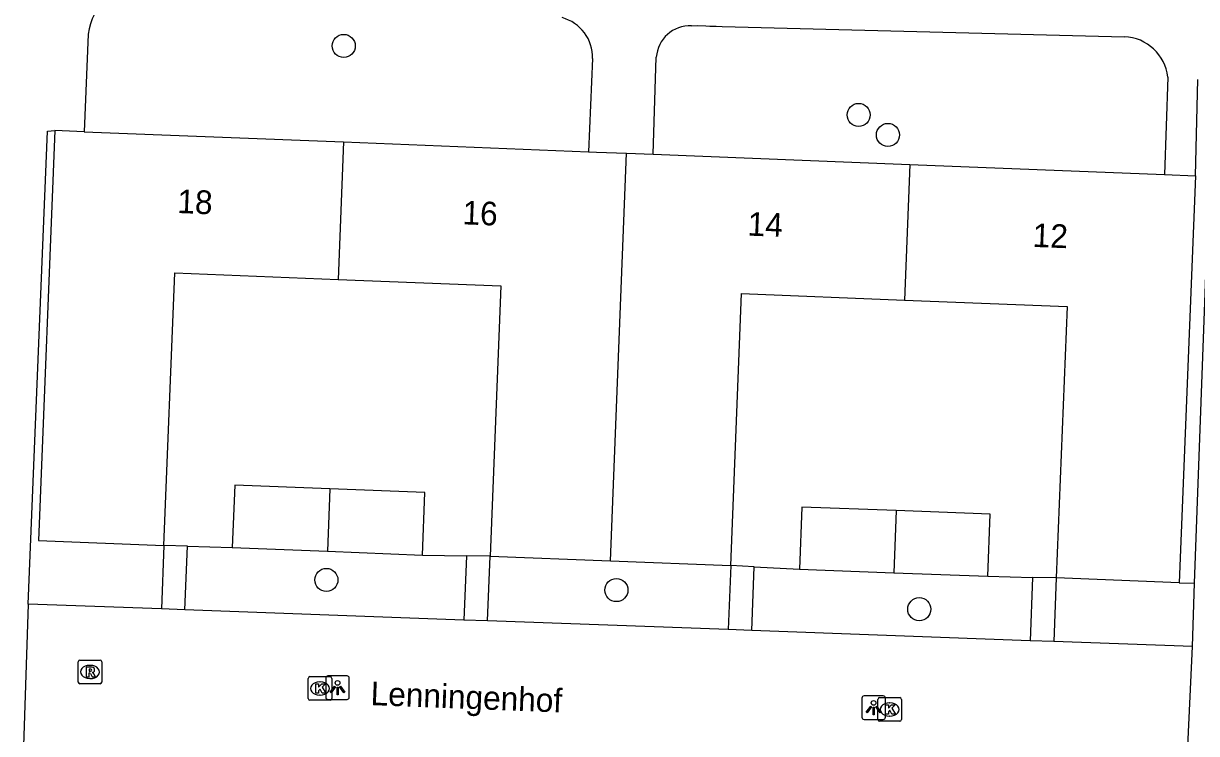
# Model space of a CAD drawing. Extents: x 160787 to 161428, y 386828 to 387483.
# Drawn here: x 161186.98 to 161236.62, y 387037.65 to 387067.7 of the extents above; entities that cross this region are included whole.
import ezdxf

# ---------------------------------------------------------------- set-up
doc = ezdxf.new("R2010")
doc.units = 0
for name, color, linetype in [('IMGEO_Boom', 7, 'Continuous'), ('IMGEO_Groenvoorziening', 7, 'Continuous'), ('IMGEO_Kolk', 7, 'Continuous'), ('IMGEO_Lichtpunt', 7, 'Continuous'), ('IMGEO_Openbare_ruimte_label', 7, 'Continuous'), ('IMGEO_Pand', 7, 'Continuous'), ('IMGEO_Pand_nummerreeks', 7, 'Continuous'), ('IMGEO_Rioolput', 7, 'Continuous'), ('IMGEO_Voetpad_open', 7, 'Continuous')]:
    doc.layers.add(name, color=color, linetype=linetype)

msp = doc.modelspace()

# ---------------------------------------------------------------- linework, layer by layer
at = {"layer": 'IMGEO_Boom'}
for centre in [(161200.531, 387066.744), (161222.319, 387063.825), (161223.558, 387062.978), (161199.795, 387044.146), (161212.067, 387043.717), (161224.883, 387042.909)]:
    msp.add_circle(centre, 0.489, dxfattribs=at)
at = {"layer": 'IMGEO_Groenvoorziening'}
for points in [[(161193.92, 387045.577), (161195.817, 387045.517)], [(161203.862, 387045.199), (161205.724, 387045.174)], [(161217.902, 387044.703), (161219.82, 387044.6)], [(161227.788, 387044.301), (161229.681, 387044.255)], [(161235.886, 387044.024), (161236.536, 387044.01)]]:
    msp.add_lwpolyline(points, dxfattribs=at)
at = {"layer": 'IMGEO_Kolk'}
for p, q in [((161199.026, 387039.129), (161199.026, 387039.981)), ((161199.101, 387040.055), (161199.953, 387040.055)), ((161200.027, 387039.981), (161200.027, 387039.129)), ((161199.514, 387039.835), (161199.539, 387039.835)), ((161199.953, 387039.055), (161199.101, 387039.055)), ((161199.537, 387039.275), (161199.512, 387039.275)), ((161223.131, 387038.241), (161223.131, 387039.093)), ((161223.206, 387039.167), (161224.058, 387039.167)), ((161224.132, 387039.093), (161224.132, 387038.241)), ((161223.619, 387038.947), (161223.644, 387038.947)), ((161224.058, 387038.167), (161223.206, 387038.167)), ((161223.642, 387038.387), (161223.617, 387038.387))]:
    msp.add_line(p, q, dxfattribs=at)
for points in [[(161199.026, 387039.129), (161199.026, 387039.981)], [(161199.101, 387040.055), (161199.953, 387040.055)], [(161200.027, 387039.981), (161200.027, 387039.129)], [(161199.347, 387039.755), (161199.47, 387039.755), (161199.47, 387039.604), (161199.6, 387039.755), (161199.764, 387039.755), (161199.618, 387039.604), (161199.771, 387039.355), (161199.619, 387039.355), (161199.534, 387039.519), (161199.47, 387039.452), (161199.47, 387039.355), (161199.347, 387039.355), (161199.347, 387039.755)], [(161199.953, 387039.055), (161199.101, 387039.055)], [(161223.131, 387038.241), (161223.131, 387039.093)], [(161223.206, 387039.167), (161224.058, 387039.167)], [(161224.132, 387039.093), (161224.132, 387038.241)], [(161223.452, 387038.867), (161223.575, 387038.867), (161223.575, 387038.716), (161223.705, 387038.867), (161223.869, 387038.867), (161223.723, 387038.716), (161223.876, 387038.467), (161223.724, 387038.467), (161223.639, 387038.631), (161223.575, 387038.564), (161223.575, 387038.467), (161223.452, 387038.467), (161223.452, 387038.867)], [(161224.058, 387038.167), (161223.206, 387038.167)]]:
    msp.add_lwpolyline(points, dxfattribs=at)
for centre, start, end in [((161199.103, 387039.979), 91.552, 178.448), ((161199.103, 387039.979), 91.552, 178.448), ((161199.951, 387039.979), 1.552, 88.448), ((161199.951, 387039.979), 1.552, 88.448), ((161199.103, 387039.131), 181.552, 268.448), ((161199.103, 387039.131), 181.552, 268.448), ((161199.951, 387039.131), 271.552, 358.448), ((161199.951, 387039.131), 271.552, 358.448), ((161223.208, 387039.091), 91.552, 178.448), ((161223.208, 387039.091), 91.552, 178.448), ((161224.056, 387039.091), 1.552, 88.448), ((161224.056, 387039.091), 1.552, 88.448), ((161223.208, 387038.243), 181.552, 268.448), ((161223.208, 387038.243), 181.552, 268.448), ((161224.056, 387038.243), 271.552, 358.448), ((161224.056, 387038.243), 271.552, 358.448)]:
    msp.add_arc(centre, 0.0765, start, end, dxfattribs=at)
for centre, major_axis, ratio, start_param, end_param in [((161199.513, 387039.555), (-0.387, 0.002), 0.722429, 4.712389, 7.853982), ((161199.538, 387039.555), (-0.39, 0.002), 0.717154, 1.570796, 4.712389), ((161223.618, 387038.667), (-0.387, 0.002), 0.722429, 4.712389, 7.853982), ((161223.643, 387038.667), (-0.39, 0.002), 0.717154, 1.570796, 4.712389)]:
    msp.add_ellipse(centre, major_axis=major_axis, ratio=ratio, start_param=start_param, end_param=end_param, dxfattribs=at)
at = {"layer": 'IMGEO_Lichtpunt'}
for p, q in [((161199.77, 387039.994), (161199.77, 387039.187)), ((161199.77, 387039.994), (161199.77, 387039.187)), ((161200.672, 387040.089), (161199.864, 387040.089)), ((161200.672, 387040.089), (161199.864, 387040.089)), ((161200.766, 387039.187), (161200.766, 387039.994)), ((161200.766, 387039.187), (161200.766, 387039.994)), ((161199.864, 387039.093), (161200.672, 387039.093)), ((161199.864, 387039.093), (161200.672, 387039.093)), ((161222.454, 387039.148), (161222.454, 387038.341)), ((161222.454, 387039.148), (161222.454, 387038.341)), ((161223.356, 387039.243), (161222.548, 387039.243)), ((161223.356, 387039.243), (161222.548, 387039.243)), ((161223.45, 387038.341), (161223.45, 387039.148)), ((161223.45, 387038.341), (161223.45, 387039.148)), ((161222.548, 387038.247), (161223.356, 387038.247)), ((161222.548, 387038.247), (161223.356, 387038.247))]:
    msp.add_line(p, q, dxfattribs=at)
for points in [[(161200.144, 387039.658), (161200.183, 387039.63), (161199.995, 387039.368), (161199.957, 387039.395), (161200.144, 387039.658)], [(161200.246, 387039.61), (161200.293, 387039.61), (161200.293, 387039.288), (161200.246, 387039.288), (161200.246, 387039.61)], [(161200.356, 387039.63), (161200.394, 387039.657), (161200.581, 387039.395), (161200.542, 387039.367), (161200.356, 387039.63)], [(161222.828, 387038.812), (161222.867, 387038.784), (161222.679, 387038.522), (161222.641, 387038.549), (161222.828, 387038.812)], [(161222.93, 387038.764), (161222.977, 387038.764), (161222.977, 387038.442), (161222.93, 387038.442), (161222.93, 387038.764)], [(161223.04, 387038.784), (161223.078, 387038.811), (161223.265, 387038.549), (161223.226, 387038.521), (161223.04, 387038.784)]]:
    msp.add_lwpolyline(points, dxfattribs=at)
for centre in [(161200.269, 387039.792), (161222.953, 387038.946)]:
    msp.add_circle(centre, 0.0994, dxfattribs=at)
for centre, start, end in [((161199.864, 387039.994), 90, 180), ((161199.864, 387039.994), 90, 180), ((161200.672, 387039.994), 0, 90), ((161200.672, 387039.994), 0, 90), ((161199.864, 387039.187), 180, 270), ((161199.864, 387039.187), 180, 270), ((161200.672, 387039.187), 270, 0), ((161200.672, 387039.187), 270, 360), ((161222.548, 387039.148), 90, 180), ((161222.548, 387039.148), 90, 180), ((161223.356, 387039.148), 0, 90), ((161223.356, 387039.148), 0, 90), ((161222.548, 387038.341), 180, 270), ((161222.548, 387038.341), 180, 270), ((161223.356, 387038.341), 270, 0), ((161223.356, 387038.341), 270, 360)]:
    msp.add_arc(centre, 0.0946, start, end, dxfattribs=at)
at = {"layer": 'IMGEO_Pand'}
for points in [[(161188.306, 387063.164), (161187.619, 387045.819), (161192.921, 387045.609)], [(161189.542, 387063.115), (161188.306, 387063.164)], [(161189.542, 387063.115), (161200.525, 387062.68)], [(161200.525, 387062.68), (161200.294, 387056.867)], [(161200.525, 387062.68), (161210.887, 387062.27)], [(161210.887, 387062.27), (161211.231, 387062.256), (161212.499, 387062.206)], [(161211.815, 387044.958), (161212.499, 387062.206)], [(161212.499, 387062.206), (161213.62, 387062.161)], [(161213.62, 387062.161), (161224.491, 387061.73)], [(161224.491, 387061.73), (161224.263, 387055.99)], [(161224.491, 387061.73), (161235.259, 387061.304)], [(161235.259, 387061.304), (161236.569, 387061.252)], [(161236.569, 387061.252), (161235.886, 387044.024)], [(161192.921, 387045.609), (161193.378, 387057.141), (161200.294, 387056.867)], [(161200.294, 387056.867), (161207.177, 387056.594), (161206.724, 387045.16)], [(161216.904, 387044.757), (161217.36, 387056.264), (161224.263, 387055.99)], [(161224.263, 387055.99), (161231.136, 387055.718), (161230.681, 387044.231)], [(161199.942, 387048.004), (161195.922, 387048.163), (161195.817, 387045.517)], [(161199.942, 387048.004), (161199.837, 387045.358)], [(161203.862, 387045.199), (161203.967, 387047.845), (161199.942, 387048.004)], [(161223.909, 387047.082), (161219.919, 387047.232), (161219.82, 387044.6)], [(161223.909, 387047.082), (161223.805, 387044.45)], [(161227.788, 387044.301), (161227.887, 387046.933), (161223.909, 387047.082)], [(161195.817, 387045.517), (161199.837, 387045.358)], [(161199.837, 387045.358), (161203.862, 387045.199)], [(161206.724, 387045.16), (161211.815, 387044.958)], [(161211.815, 387044.958), (161216.904, 387044.757)], [(161219.82, 387044.6), (161223.805, 387044.45)], [(161223.805, 387044.45), (161227.788, 387044.301)], [(161235.886, 387044.024), (161230.681, 387044.231)]]:
    msp.add_lwpolyline(points, dxfattribs=at)
at = {"layer": 'IMGEO_Rioolput'}
for p, q in [((161189.294, 387039.827), (161189.294, 387040.679)), ((161189.369, 387040.753), (161190.221, 387040.753)), ((161189.782, 387040.533), (161189.807, 387040.533)), ((161190.295, 387040.679), (161190.295, 387039.827)), ((161189.805, 387039.973), (161189.78, 387039.973)), ((161190.221, 387039.753), (161189.369, 387039.753))]:
    msp.add_line(p, q, dxfattribs=at)
for points in [[(161189.294, 387039.827), (161189.294, 387040.679)], [(161189.369, 387040.753), (161190.221, 387040.753)], [(161190.295, 387040.679), (161190.295, 387039.827)], [(161189.883, 387040.451), (161189.631, 387040.453), (161189.631, 387040.053)], [(161189.631, 387040.053), (161189.755, 387040.053), (161189.755, 387040.215), (161189.766, 387040.215)], [(161189.809, 387040.372), (161189.755, 387040.372), (161189.755, 387040.291)], [(161189.755, 387040.291), (161189.807, 387040.291)], [(161189.813, 387040.186), (161189.884, 387040.053), (161190.024, 387040.053), (161189.959, 387040.179)], [(161190.221, 387039.753), (161189.369, 387039.753)]]:
    msp.add_lwpolyline(points, dxfattribs=at)
for centre, radius, start, end in [((161189.371, 387040.677), 0.0765, 91.552, 178.448), ((161189.371, 387040.677), 0.0765, 91.552, 178.448), ((161190.219, 387040.677), 0.0765, 1.552, 88.448), ((161190.219, 387040.677), 0.0765, 1.552, 88.448), ((161189.765, 387040.162), 0.0533, 26.0293, 88.6989), ((161189.791, 387040.48), 0.19, 274.7715, 282.9687), ((161189.815, 387040.276), 0.0964, 77.0061, 93.1865), ((161189.829, 387040.333), 0.0378, 276.6634, 79.6772), ((161189.882, 387040.341), 0.109, 350.3612, 89.416), ((161189.88, 387040.341), 0.112, 277.5842, 350.9817), ((161189.864, 387040.126), 0.108, 29.5134, 73.7905), ((161189.371, 387039.829), 0.0765, 181.552, 268.448), ((161189.371, 387039.829), 0.0765, 181.552, 268.448), ((161190.219, 387039.829), 0.0765, 271.552, 358.448), ((161190.219, 387039.829), 0.0765, 271.552, 358.448)]:
    msp.add_arc(centre, radius, start, end, dxfattribs=at)
for centre, major_axis, ratio, start_param, end_param in [((161189.781, 387040.253), (-0.387, 0.002), 0.722429, 4.712389, 7.853982), ((161189.806, 387040.253), (-0.39, 0.002), 0.717154, 1.570796, 4.712389)]:
    msp.add_ellipse(centre, major_axis=major_axis, ratio=ratio, start_param=start_param, end_param=end_param, dxfattribs=at)
at = {"layer": 'IMGEO_Voetpad_open'}
for points in [[(161215.242, 387067.596), (161215.502, 387067.606), (161215.853, 387067.591), (161216.028, 387067.586), (161216.286, 387067.58), (161216.542, 387067.573), (161233.567, 387067.133)], [(161189.72, 387067.248), (161189.542, 387063.115)], [(161211.063, 387066.207), (161210.887, 387062.27)], [(161213.62, 387062.161), (161213.757, 387066.263)], [(161235.405, 387065.43), (161235.259, 387061.304)], [(161236.569, 387061.252), (161236.665, 387065.323)], [(161187.174, 387043.125), (161187.992, 387063.144), (161188.306, 387063.164)], [(161236.536, 387044.01), (161237.164, 387061.255), (161239.655, 387061.146)], [(161192.921, 387045.609), (161192.814, 387042.919)], [(161193.92, 387045.577), (161192.921, 387045.609)], [(161193.813, 387042.882), (161193.92, 387045.577)], [(161205.724, 387045.174), (161205.616, 387042.451)], [(161206.724, 387045.16), (161205.724, 387045.174)], [(161206.615, 387042.415), (161206.724, 387045.16)], [(161216.904, 387044.757), (161216.796, 387042.043)], [(161217.902, 387044.703), (161216.904, 387044.757)], [(161217.795, 387042.006), (161217.902, 387044.703)], [(161229.681, 387044.255), (161229.576, 387041.576)], [(161230.681, 387044.231), (161229.681, 387044.255)], [(161230.681, 387044.231), (161230.575, 387041.539)], [(161236.438, 387041.325), (161236.536, 387044.01)], [(161187.174, 387043.125), (161186.979, 387037.128)], [(161192.814, 387042.919), (161187.174, 387043.125)], [(161193.813, 387042.882), (161192.814, 387042.919)], [(161205.616, 387042.451), (161193.813, 387042.882)], [(161206.615, 387042.415), (161205.616, 387042.451)], [(161216.796, 387042.043), (161206.615, 387042.415)], [(161217.795, 387042.006), (161216.796, 387042.043)], [(161229.576, 387041.576), (161217.795, 387042.006)], [(161230.575, 387041.539), (161229.576, 387041.576)], [(161236.438, 387041.325), (161230.575, 387041.539)], [(161236.191, 387035.895), (161236.438, 387041.325)]]:
    msp.add_lwpolyline(points, dxfattribs=at)
for centre, radius, start, end in [((161191.848, 387067.023), 2.14, 126.4695, 173.9748), ((161209.309, 387066.25), 1.754, 358.5977, 74.8458), ((161215.181, 387066.17), 1.427, 87.543, 176.282), ((161233.482, 387065.198), 1.937, 6.8705, 87.4961)]:
    msp.add_arc(centre, radius, start, end, dxfattribs=at)

# ---------------------------------------------------------------- texts
at = {"layer": 'IMGEO_Openbare_ruimte_label'}
msp.add_text('Lenningenhof', height=1, rotation=357.7644, dxfattribs=at).set_placement((161201.655, 387038.853))
at = {"layer": 'IMGEO_Pand_nummerreeks'}
for s, rotation, p in [('18', 357.7313, (161193.477, 387059.676)), ('16', 357.7311, (161205.54, 387059.198)), ('14', 357.7313, (161217.606, 387058.72)), ('12', 357.7313, (161229.668, 387058.242))]:
    msp.add_text(s, height=1, rotation=rotation, dxfattribs=at).set_placement(p)

doc.saveas('drawing.dxf')
